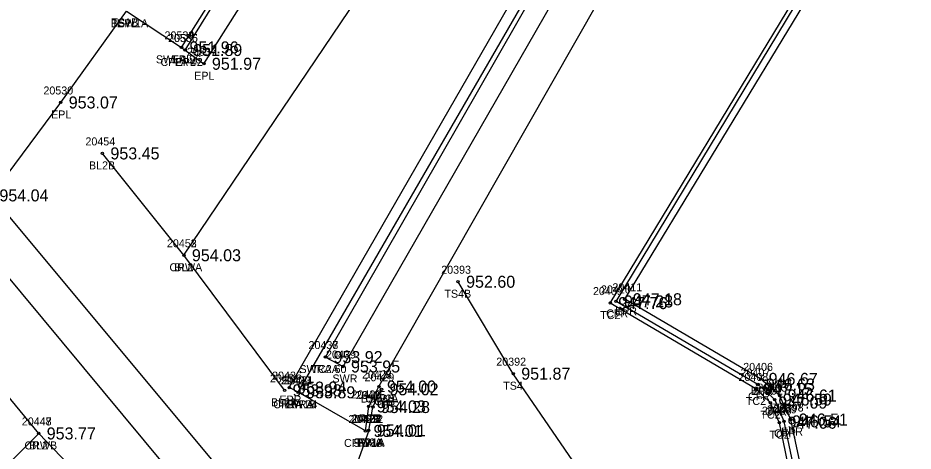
# Model space of a CAD drawing. Extents: x 1576181 to 1577685, y 1099396 to 1101490.
# Drawn here: x 1576415.2 to 1576527.1, y 1099611 to 1099665.2 of the extents above; entities that cross this region are included whole.
import ezdxf

# ---------------------------------------------------------------- set-up
doc = ezdxf.new("R2010")
doc.units = 0
for name, color, linetype in [('RD_DTM_BkLn1', 7, 'Continuous'), ('RD_DTM_BkLn2', 7, 'Continuous'), ('RD_DTM_BkLn_txCode', 7, 'Continuous'), ('RD_EX_Conc', 7, 'Continuous'), ('RD_EX_Conc_txCode', 7, 'Continuous'), ('RD_EX_RailRoad', 7, 'Continuous'), ('RD_EX_Road', 7, 'Continuous'), ('RD_EX_Road_txCode', 7, 'Continuous'), ('RD_EX_TX_Conc_ELEV', 7, 'Continuous'), ('RD_EX_TX_Misc_ELEV', 7, 'Continuous'), ('RD_EX_TX_RailRoad_ELEV', 7, 'Continuous'), ('RD_EX_TX_Road_ELEV', 7, 'Continuous'), ('RD_HC_Survey_ELEV', 7, 'Continuous'), ('RD_HC_Survey_txCode', 7, 'Continuous'), ('RD_SMD_Locator', 7, 'Continuous')]:
    doc.layers.add(name, color=color, linetype=linetype)

msp = doc.modelspace()

# ---------------------------------------------------------------- linework, layer by layer
at = {"layer": 'RD_DTM_BkLn1'}
for points in [[(1576435.96, 1099635.47), (1576469.98, 1099685.91), (1576496.51, 1099728.46), (1576522.67, 1099770.85), (1576549.06, 1099813.4), (1576563.36, 1099837.2), (1576575.09, 1099855.95), (1576600.75, 1099898.96), (1576625.57, 1099942.14), (1576652.37, 1099988.91), (1576675.03, 1100029.12), (1576699.51, 1100072.44), (1576723.52, 1100115.7), (1576748.08, 1100158.53), (1576774.13, 1100203.85), (1576797.97, 1100246.52), (1576822.46, 1100289.82), (1576846.93, 1100333.35), (1576871.37, 1100376.46), (1576888.27, 1100406.22)], [(1576448.54, 1099618.58), (1576435.96, 1099635.47), (1576425.78, 1099648.21)], [(1576442.61, 1099587.26), (1576417.82, 1099613.19), (1576402.2, 1099632.12), (1576392.54, 1099647.43)], [(1576355.86, 1099557.44), (1576389.32, 1099587.93), (1576411.06, 1099606.41), (1576417.82, 1099613.19)]]:
    msp.add_lwpolyline(points, dxfattribs=at)
at = {"layer": 'RD_DTM_BkLn2'}
for points in [[(1576453.65, 1099622.74), (1576484.93, 1099677.43), (1576510.27, 1099720.56), (1576537.09, 1099763.56), (1576564.3, 1099806.82), (1576572.37, 1099816.55), (1576577.32, 1099819.84)], [(1576511.92, 1099607.05), (1576510.37, 1099614.53), (1576509.23, 1099617.04), (1576507.41, 1099618.75), (1576489.23, 1099629.49), (1576513, 1099668.8), (1576536.11, 1099706.87), (1576550.83, 1099731.33)], [(1576610.37, 1099493.15), (1576590.84, 1099502.32), (1576544.26, 1099533.46), (1576511.88, 1099559.41), (1576487.01, 1099606.17), (1576477.11, 1099620.66), (1576470.22, 1099632.16)], [(1576459.06, 1099613.56), (1576459.57, 1099616.49), (1576460.65, 1099618.71)]]:
    msp.add_lwpolyline(points, dxfattribs=at)
at = {"layer": 'RD_EX_Conc'}
for p, q in [((1576436.12, 1099661.14), (1576443.97, 1099673.78)), ((1576458.65, 1099613.5), (1576450.24, 1099618.33))]:
    msp.add_line(p, q, dxfattribs=at)
for points in [[(1576435.66, 1099661.47), (1576443.54, 1099673.97), (1576443.97, 1099673.78), (1576456.79, 1099694.01), (1576456.14, 1099694.19), (1576458.58, 1099697.76), (1576467.89, 1099712.42), (1576470.32, 1099716.02), (1576470.74, 1099715.71), (1576484.32, 1099737.29), (1576483.81, 1099737.74), (1576485.99, 1099741.1), (1576511.43, 1099781.01), (1576536.53, 1099821.05), (1576540.61, 1099827.59), (1576541.13, 1099827.37), (1576542.92, 1099831.85), (1576542.87, 1099835.12), (1576541.33, 1099839.59)], [(1576450.24, 1099618.33), (1576484.56, 1099677.8), (1576510.13, 1099721.55), (1576536.54, 1099763.94), (1576563.69, 1099807.11), (1576571.96, 1099817.02), (1576576.78, 1099820.05)], [(1576453.65, 1099622.74), (1576455.84, 1099621.56), (1576487.04, 1099675.93), (1576513, 1099720.16), (1576539.03, 1099761.82), (1576566.5, 1099805.38), (1576570.9, 1099812.6)], [(1576460.33, 1099619.05), (1576491.05, 1099673.04), (1576516.28, 1099716.12), (1576543.31, 1099759.42), (1576570.5, 1099802.59), (1576575.6, 1099809.12)], [(1576512.55, 1099607.18), (1576510.94, 1099614.7), (1576509.78, 1099617.42), (1576507.67, 1099619.31), (1576489.95, 1099629.7), (1576513.43, 1099668.52), (1576536.7, 1099706.66), (1576550.99, 1099730.5)], [(1576458.65, 1099613.5), (1576459.05, 1099616.57), (1576460.33, 1099619.05)]]:
    msp.add_lwpolyline(points, dxfattribs=at)
at = {"layer": 'RD_EX_RailRoad'}
for points in [[(1576588.64, 1099429.74), (1576556.82, 1099468.27), (1576525.53, 1099505.93), (1576492.19, 1099546.33), (1576461.17, 1099583.65), (1576447.93, 1099599.71), (1576411.91, 1099642.96), (1576369.31, 1099694.21), (1576336.53, 1099733.7), (1576300.55, 1099777.04), (1576258.58, 1099827.59)], [(1576584.91, 1099426.47), (1576552.99, 1099465.14), (1576521.86, 1099502.63), (1576488.35, 1099543.2), (1576457.44, 1099580.52), (1576443.75, 1099596.96), (1576408.06, 1099639.92), (1576365.56, 1099691.12), (1576332.82, 1099730.47), (1576296.82, 1099773.87), (1576254.94, 1099824.3)]]:
    msp.add_lwpolyline(points, dxfattribs=at)
at = {"layer": 'RD_EX_Road'}
for points in [[(1576217.78, 1099763.81), (1576263.48, 1099736.46), (1576283.45, 1099724.57), (1576282.38, 1099722.88), (1576302.5, 1099710.8), (1576345.46, 1099684.21), (1576368.62, 1099668.36), (1576383.76, 1099654.94), (1576386.09, 1099656.79), (1576408.06, 1099639.92), (1576408.06, 1099639.92), (1576411.91, 1099642.96), (1576420.57, 1099654.58), (1576428.78, 1099665.98), (1576435.66, 1099661.47), (1576436.12, 1099661.14), (1576438.46, 1099659.42), (1576459.37, 1099692.41), (1576486.6, 1099735.59), (1576512.85, 1099776.73), (1576539.46, 1099818.98), (1576543.78, 1099825.47), (1576541.42, 1099827.15), (1576542.92, 1099831.85)], [(1576450.24, 1099618.33), (1576449.12, 1099618.92), (1576483.24, 1099678.31), (1576508.19, 1099720.98), (1576535.39, 1099764.56), (1576562.56, 1099807.86), (1576568.65, 1099815.29), (1576571.43, 1099817.5), (1576576.56, 1099821.02), (1576582.03, 1099822.66), (1576588.16, 1099823.79), (1576596.81, 1099822.84), (1576604.56, 1099819.9), (1576624.36, 1099808.15), (1576638.14, 1099802.71)], [(1576513.37, 1099607.48), (1576511.79, 1099614.93), (1576510.39, 1099617.93), (1576508.02, 1099620.01), (1576491.05, 1099629.97), (1576514.12, 1099668.03), (1576537.42, 1099706.25), (1576551.23, 1099729.3)], [(1576459.06, 1099613.56), (1576454.1, 1099599.68), (1576447.93, 1099599.71), (1576443.75, 1099596.96)]]:
    msp.add_lwpolyline(points, dxfattribs=at)
at = {"layer": 'RD_SMD_Locator'}
for centre in [(1576435.66, 1099661.47), (1576435.66, 1099661.47), (1576436.12, 1099661.14), (1576436.12, 1099661.14), (1576438.46, 1099659.42), (1576420.57, 1099654.58), (1576425.78, 1099648.21), (1576435.96, 1099635.47), (1576435.96, 1099635.47), (1576470.22, 1099632.16), (1576489.95, 1099629.7), (1576491.05, 1099629.97), (1576489.23, 1099629.49), (1576453.65, 1099622.74), (1576453.65, 1099622.74), (1576455.84, 1099621.56), (1576477.11, 1099620.66), (1576508.02, 1099620.01), (1576448.54, 1099618.58), (1576449.12, 1099618.92), (1576460.33, 1099619.05), (1576460.33, 1099619.05), (1576460.65, 1099618.71), (1576507.41, 1099618.75), (1576507.67, 1099619.31), (1576450.24, 1099618.33), (1576450.24, 1099618.33), (1576450.24, 1099618.33), (1576509.78, 1099617.42), (1576510.39, 1099617.93), (1576459.05, 1099616.57), (1576459.57, 1099616.49), (1576509.23, 1099617.04), (1576510.37, 1099614.53), (1576510.94, 1099614.7), (1576511.79, 1099614.93), (1576417.82, 1099613.19), (1576417.82, 1099613.19), (1576458.65, 1099613.5), (1576458.65, 1099613.5), (1576459.06, 1099613.56), (1576459.06, 1099613.56)]:
    msp.add_circle(centre, 0.15, dxfattribs=at)

# ---------------------------------------------------------------- texts
at = {"layer": 'RD_DTM_BkLn_txCode'}
for s, p in [('TS1B', (1576426.91, 1099664.09)), ('20454', (1576423.66, 1099649.21)), ('BL2B', (1576424.1, 1099646.21)), ('20452', (1576433.84, 1099636.47)), ('BL2', (1576434.75, 1099633.47)), ('20393', (1576468.11, 1099633.16)), ('TS4B', (1576468.51, 1099630.16)), ('20392', (1576474.99, 1099621.66)), ('20451', (1576446.71, 1099619.58)), ('TS4', (1576475.86, 1099618.66)), ('BL2A', (1576446.85, 1099616.58)), ('20447', (1576415.71, 1099614.19)), ('BL2', (1576416.62, 1099611.19))]:
    msp.add_text(s, height=1, dxfattribs=at).set_placement(p)
at = {"layer": 'RD_EX_Conc_txCode'}
for s, p in [('BSW1A', (1576426.81, 1099663.98)), ('20534', (1576433.54, 1099662.47)), ('20535', (1576434, 1099662.14)), ('SWLA 96', (1576432.47, 1099659.47)), ('CFLA 42', (1576433.04, 1099659.14)), ('20409', (1576487.07, 1099630.49)), ('20410', (1576488.07, 1099630.7)), ('CFR', (1576488.72, 1099627.7)), ('TC2', (1576487.98, 1099627.49)), ('20437', (1576451.53, 1099623.74)), ('20438', (1576451.53, 1099623.74)), ('20439', (1576453.72, 1099622.56)), ('SWRA 60', (1576450.4, 1099620.74)), ('TC2A', (1576451.91, 1099620.74)), ('20427', (1576458.21, 1099620.05)), ('20428', (1576458.21, 1099620.05)), ('20407', (1576505.51, 1099620.31)), ('20423', (1576448.12, 1099619.33)), ('20431', (1576448.4, 1099619.33)), ('SWR', (1576454.52, 1099619.56)), ('20429', (1576458.53, 1099619.71)), ('20408', (1576505.25, 1099619.75)), ('20426', (1576456.9, 1099617.57)), ('20402', (1576507.07, 1099618.04)), ('20403', (1576507.62, 1099618.42)), ('20425', (1576457.45, 1099617.49)), ('BSW2A', (1576458.08, 1099617.05)), ('CFRB', (1576458.63, 1099617.05)), ('TC2B', (1576458.93, 1099616.71)), ('TC2', (1576506.17, 1099616.75)), ('CFR', (1576506.44, 1099617.31)), ('CFRA 24', (1576447.13, 1099616.33)), ('SW1B', (1576448.75, 1099616.33)), ('20400', (1576508.17, 1099615.53)), ('CFR', (1576508.55, 1099615.42)), ('20399', (1576508.82, 1099615.7)), ('20422', (1576456.53, 1099614.5)), ('20421', (1576456.81, 1099614.5)), ('20424', (1576456.94, 1099614.56)), ('CFR', (1576457.82, 1099614.57)), ('TC2', (1576458.32, 1099614.49)), ('TC2', (1576507.99, 1099615.04)), ('TC2', (1576509.13, 1099612.53)), ('CFR', (1576509.71, 1099612.7)), ('CFRA 6', (1576455.97, 1099611.5)), ('SW1A', (1576457.15, 1099611.5)), ('TC2A', (1576457.33, 1099611.56))]:
    msp.add_text(s, height=1, dxfattribs=at).set_placement(p)
at = {"layer": 'RD_EX_Road_txCode'}
for s, p in [('EPL', (1576427.58, 1099663.98)), ('20533', (1576433.54, 1099662.47)), ('20536', (1576433.98, 1099662.14)), ('20537', (1576436.34, 1099660.42)), ('EPL', (1576434.45, 1099659.47)), ('EPL', (1576434.92, 1099659.14)), ('EPL', (1576437.25, 1099657.42)), ('20530', (1576418.41, 1099655.58)), ('EPL', (1576419.37, 1099652.58)), ('20411', (1576489.5, 1099630.97)), ('EPR', (1576489.82, 1099627.97)), ('20406', (1576505.84, 1099621.01)), ('20436', (1576446.98, 1099619.92)), ('20430', (1576448.08, 1099619.33)), ('20404', (1576508.24, 1099618.93)), ('EPR', (1576506.79, 1099618.01)), ('EPR', (1576447.89, 1099616.92)), ('EPRA', (1576448.52, 1099616.33)), ('EPR', (1576509.17, 1099615.93)), ('20398', (1576509.67, 1099615.93)), ('20432', (1576456.94, 1099614.56)), ('EPR', (1576510.56, 1099612.93)), ('EP1A', (1576457.65, 1099611.56))]:
    msp.add_text(s, height=1, dxfattribs=at).set_placement(p)
at = {"layer": 'RD_EX_TX_Conc_ELEV'}
for s, p in [('951.96', (1576436.66, 1099660.72)), ('951.89', (1576437.12, 1099660.39)), ('947.76', (1576490.23, 1099628.74)), ('947.28', (1576490.95, 1099628.95)), ('953.92', (1576454.65, 1099621.99)), ('953.92', (1576454.65, 1099621.99)), ('953.95', (1576456.84, 1099620.81)), ('954.00', (1576461.33, 1099618.3)), ('954.00', (1576461.33, 1099618.3)), ('946.63', (1576508.67, 1099618.56)), ('953.89', (1576451.24, 1099617.58)), ('953.89', (1576451.24, 1099617.58)), ('954.02', (1576461.65, 1099617.96)), ('947.15', (1576508.41, 1099618)), ('947.09', (1576510.23, 1099616.29)), ('946.59', (1576510.78, 1099616.67)), ('954.03', (1576460.05, 1099615.82)), ('954.28', (1576460.57, 1099615.74)), ('947.06', (1576511.37, 1099613.78)), ('946.54', (1576511.94, 1099613.95)), ('954.01', (1576459.65, 1099612.75)), ('954.01', (1576459.65, 1099612.75)), ('954.01', (1576460.06, 1099612.81))]:
    msp.add_text(s, height=1.5, dxfattribs=at).set_placement(p)
at = {"layer": 'RD_EX_TX_Misc_ELEV'}
for s, p in [('953.45', (1576426.78, 1099647.46)), ('954.03', (1576436.96, 1099634.72)), ('952.60', (1576471.22, 1099631.41)), ('951.87', (1576478.11, 1099619.91)), ('953.98', (1576449.54, 1099617.83)), ('953.77', (1576418.82, 1099612.44))]:
    msp.add_text(s, height=1.5, dxfattribs=at).set_placement(p)
at = {"layer": 'RD_EX_TX_RailRoad_ELEV'}
msp.add_text('954.04', height=1.5, dxfattribs=at).set_placement((1576412.91, 1099642.21))
at = {"layer": 'RD_EX_TX_Road_ELEV'}
for s, p in [('951.96', (1576436.66, 1099660.72)), ('951.89', (1576437.12, 1099660.39)), ('951.97', (1576439.46, 1099658.67)), ('953.07', (1576421.57, 1099653.83)), ('954.04', (1576412.91, 1099642.21)), ('947.18', (1576492.05, 1099629.22)), ('953.94', (1576450.12, 1099618.17)), ('946.67', (1576509.02, 1099619.26)), ('953.89', (1576451.24, 1099617.58)), ('946.61', (1576511.39, 1099617.18)), ('946.51', (1576512.79, 1099614.18)), ('954.01', (1576460.06, 1099612.81))]:
    msp.add_text(s, height=1.5, dxfattribs=at).set_placement(p)
at = {"layer": 'RD_HC_Survey_ELEV'}
for s, p in [('954.03', (1576436.96, 1099634.72)), ('953.77', (1576418.82, 1099612.44))]:
    msp.add_text(s, height=1.5, dxfattribs=at).set_placement(p)
at = {"layer": 'RD_HC_Survey_txCode'}
for s, p in [('20453', (1576433.84, 1099636.47)), ('CRWA', (1576434.16, 1099633.47)), ('20448', (1576415.71, 1099614.19)), ('CRWB', (1576416.04, 1099611.19))]:
    msp.add_text(s, height=1, dxfattribs=at).set_placement(p)

doc.saveas('drawing.dxf')
